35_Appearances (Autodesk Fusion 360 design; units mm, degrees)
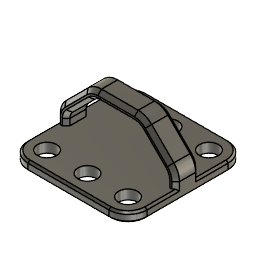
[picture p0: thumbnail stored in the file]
part number: 2026-07-17-16-36-47-156
sketch "Sketch1" plane through (0, 0, 0) normal (0, 0, 1) x axis (1, 0, 0)
  line L1 (-62.5, -12.5) -> (62.5, -12.5)
  line L2 (-62.5, 12.5) -> (-62.5, -12.5)
  line L3 (62.5, 12.5) -> (-62.5, 12.5)
  line L4 (62.5, -12.5) -> (62.5, 12.5)
  line L5 (-62.5, 12.5) -> (62.5, -12.5)
  line L6 (62.5, 12.5) -> (-62.5, -12.5)
  point P6 (0, 0)
  point P1 (0, 0)
  point P4 (-62.5, 12.5)
  point P5 (62.5, 12.5)
  point P3 (-62.5, -12.5)
  horizontal L1
  perpendicular L1 L2
  parallel L1 L3
  parallel L2 L4
  coincident L5 P6
  coincident L6 P6
  coincident P1 P6
  dimension "d1" distance P4 P5 = 125
  dimension "d2" distance P3 P4 = 25
extrude "Extrude1" new body sketch "Sketch1" profile of L1 L2 L3 L4 along normal blind 50
chamfer "Chamfer1" distance 35
sketch "Sketch2" plane through (0, 0, 0) normal (0, 0, -1) x axis (1, 0, 0)
  line L1 (62.5, -12.5) -> (-62.5, -12.5)
  line L2 (62.5, 12.5) -> (62.5, -12.5)
  line L3 (-62.5, 12.5) -> (62.5, 12.5)
  line L4 (-62.5, -12.5) -> (-62.5, 12.5)
  line L5 (-62.5, -62.5) -> (62.5, -62.5)
  line L6 (-62.5, 62.5) -> (-62.5, -62.5)
  line L7 (62.5, 62.5) -> (-62.5, 62.5)
  line L8 (62.5, -62.5) -> (62.5, 62.5)
  line L9 (-62.5, 62.5) -> (62.5, -62.5)
  line L10 (62.5, 62.5) -> (-62.5, -62.5)
  point P10 (0, 0)
  point P1 (0, 0)
  point P7 (-62.5, -62.5)
  point P8 (-62.5, 62.5)
  horizontal L5
  perpendicular L5 L6
  parallel L5 L7
  parallel L6 L8
  coincident L9 P10
  coincident L10 P10
  coincident P1 P10
  equal L6 L7
  dimension "d6" distance P7 P8 = 125
extrude "Extrude2" add sketch "Sketch2" profile of L1 L2 L3 L4 L5 L6 L7 L8 along normal blind 10
fillet "Fillet1" radius 20
shell "Shell1" innerThickness 10
hole "Hole1" HoleDepth 20 HoleDiameter 20 TipAngle 118
rectangular_pattern "R-Pattern1" uSpaceDistance 85 vSpaceDistance 85
fillet "Fillet2" radius 10
fillet "Fillet3" radius 20
chamfer "Chamfer2" distance 4
chamfer "Chamfer3" distance 2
